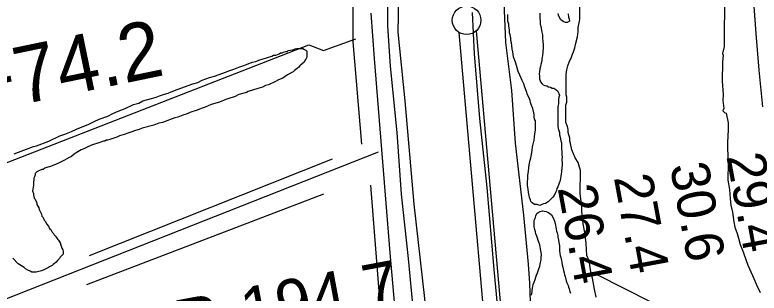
# Model space of a CAD drawing. Extents: x 3324125 to 3362000, y 600753 to 626151.
# Drawn here: x 3331428 to 3332729, y 616457 to 616943 of the extents above; entities that cross this region are included whole.
import ezdxf

# ---------------------------------------------------------------- set-up
doc = ezdxf.new("R2010")
doc.units = 0
for name, color, linetype in [('V-FLOD-BASE', 7, 'Continuous'), ('V-LEVE-TOET', 7, 'Continuous'), ('V-RIVR-RANG', 7, 'Continuous'), ('V-RIVR-RANG-IDEN', 7, 'Continuous'), ('V-ROAD-CNTR', 7, 'Continuous'), ('V-SITE-VEGE', 7, 'Continuous'), ('V-SURV-IDEN', 7, 'Continuous'), ('V-SURV-LINE', 7, 'Continuous'), ('V-TOPO-MAJR', 7, 'Continuous'), ('V-TOPO-SHOR', 7, 'Continuous')]:
    doc.layers.add(name, color=color, linetype=linetype)

msp = doc.modelspace()

# ---------------------------------------------------------------- linework, layer by layer
at = {"layer": 'V-FLOD-BASE'}
msp.add_lwpolyline([(3332227.4, 616947.5), (3332230.4, 616875.1), (3332240.2, 616761.9), (3332252.8, 616641.6), (3332265.3, 616498.5), (3332282.8, 616307), (3332296.8, 616124.8), (3332307.5, 615977.1), (3332326, 615776.8), (3332341.5, 615636.1), (3332349.3, 615584.7), (3332355.5, 615546.7), (3332369.2, 615509.3), (3332410.1, 615416.8), (3332454.9, 615312.6), (3332517, 615173.9)], dxfattribs=at)
at = {"layer": 'V-LEVE-TOET'}
for points in [[(3332098.6, 616972.3), (3332097, 616912.8), (3332109.7, 616793), (3332125.4, 616612.6), (3332143.6, 616447.9), (3332162.1, 616232.5), (3332184.7, 616036.8), (3332201.7, 615777.6), (3332213.1, 615637.5), (3332221.3, 615551.1), (3332240, 615472.2), (3332264.7, 615412.5), (3332328.7, 615293.6), (3332371.9, 615197.6)], [(3332428.3, 615531.7), (3332411.2, 615588.4), (3332406.2, 615631.6), (3332397.3, 615695.8), (3332388.5, 615792.6), (3332387.1, 615828.8), (3332384.4, 615862.8), (3332375.9, 615904.9), (3332364.3, 615994), (3332362, 616032.7), (3332352.6, 616160.4), (3332351.5, 616196.6), (3332346.1, 616277.4), (3332340.9, 616323), (3332330.7, 616391.5), (3332327.8, 616474.5), (3332325.5, 616507.5), (3332317.3, 616593.3), (3332302.9, 616718.9), (3332296.5, 616811.1), (3332286, 616894.6), (3332282.9, 616965.2)]]:
    msp.add_lwpolyline(points, dxfattribs=at)
at = {"layer": 'V-ROAD-CNTR'}
for points in [[(3332050.3, 616945.8), (3332056, 616867), (3332083.1, 616527.3), (3332155.9, 615701.2), (3332162.6, 615620.8), (3332176.4, 615550.1), (3332191.1, 615490.1), (3332204, 615447.5), (3332252.4, 615333.1), (3332828.6, 614063.2)], [(3332062.8, 616703.3), (3331299.1, 616402.5), (3331283.7, 616393.5), (3331269.2, 616382.1), (3331260.5, 616370.6), (3331252.7, 616347.9), (3331246.8, 616320), (3331249.3, 616296.2), (3331258.3, 616256.3), (3331450.3, 615777.5), (3331453.2, 615748.7), (3331451.9, 615720), (3331443.3, 615699.2), (3331428.9, 615681.4), (3331411.3, 615667.7), (3331394.3, 615658.1), (3330239.3, 615193.5), (3328629.8, 614542.4), (3328220.6, 614377)]]:
    msp.add_lwpolyline(points, dxfattribs=at)
at = {"layer": 'V-SITE-VEGE'}
for points in [[(3332427.8, 616523.2), (3332426.6, 616543.8), (3332424, 616563), (3332421.3, 616578.1), (3332418.7, 616600.1), (3332418.8, 616608.3), (3332416.2, 616630.3), (3332416.4, 616671.5), (3332413.8, 616681.1), (3332412.4, 616685.2), (3332407, 616693.5), (3332401.6, 616707.2), (3332398.9, 616718.2), (3332397.6, 616722.3), (3332397.6, 616727.8), (3332394.9, 616737.4), (3332394.9, 616742.9), (3332393.6, 616748.4), (3332390.9, 616755.3), (3332391.1, 616785.5), (3332392.5, 616790.9), (3332392.6, 616799.2), (3332391.2, 616803.3), (3332391.2, 616807.4), (3332391.4, 616823.9), (3332391.4, 616829.4), (3332391.5, 616839), (3332392.9, 616847.2), (3332394.3, 616854), (3332397.1, 616862.2), (3332399.9, 616867.7), (3332402.7, 616874.6), (3332404.1, 616878.7), (3332406.8, 616885.5), (3332408.3, 616893.7), (3332411.1, 616904.7), (3332412.5, 616914.3), (3332412.6, 616921.1), (3332414, 616929.3), (3332415.4, 616934.8), (3332415.6, 616969.1)], [(3332667.9, 616959.3), (3332667.6, 616908.5), (3332667.5, 616887.9), (3332664.7, 616875.6), (3332666, 616872.8), (3332664.6, 616860.5), (3332664.3, 616827.6), (3332665.6, 616804.3), (3332665.5, 616793.3), (3332666.8, 616779.6), (3332665.4, 616775.5), (3332668.1, 616772.7), (3332670.8, 616771.3), (3332674.8, 616754.8), (3332674.8, 616742.5), (3332673.3, 616720.5), (3332673.2, 616709.6), (3332674.4, 616684.9), (3332674.2, 616654.7), (3332676.8, 616638.2), (3332678.1, 616621.8), (3332679.4, 616610.8), (3332682.1, 616598.4), (3332684.7, 616581.9), (3332686, 616572.3), (3332690.1, 616561.3), (3332692.7, 616553.1), (3332695.4, 616542.1), (3332699.5, 616532.5), (3332702.2, 616525.6), (3332708.9, 616506.3), (3332711.6, 616499.5), (3332719.7, 616482.9), (3332723.8, 616471.9), (3332730.5, 616458.2)], [(3331426.5, 616700.5), (3331434.5, 616703.6), (3331448.1, 616708.3), (3331460.8, 616713), (3331465.6, 616714.5), (3331487.2, 616722.4), (3331506.4, 616731.8), (3331515.1, 616734.9), (3331527.1, 616739.6), (3331535.9, 616743.6), (3331557.5, 616752.2), (3331566.3, 616756.9), (3331575.1, 616760.8), (3331590.2, 616766.3), (3331599, 616771), (3331608.6, 616775), (3331620.6, 616779.7), (3331635, 616786.7), (3331644.5, 616789.1), (3331651.7, 616793), (3331666.9, 616796.9), (3331674.9, 616799.2), (3331680.5, 616801.6), (3331689.2, 616804.7), (3331695.6, 616806.3), (3331701.2, 616808.6), (3331711.6, 616812.5), (3331719.6, 616815.7), (3331730.8, 616819.6), (3331738.7, 616822.7), (3331747.5, 616825), (3331755.5, 616829), (3331768.3, 616833.7), (3331777.1, 616836), (3331785, 616839.1), (3331796.2, 616843), (3331803.4, 616846.2), (3331810.6, 616848.5), (3331819.4, 616851.7), (3331826.6, 616854), (3331833, 616856.3), (3331842.5, 616860.3), (3331848.9, 616861.8), (3331854.5, 616864.2), (3331861.7, 616866.5), (3331865.7, 616867.3), (3331869.7, 616868.8), (3331876.9, 616871.2), (3331880.1, 616872.8), (3331884, 616872.7), (3331889.6, 616875.1), (3331892, 616876.7), (3331895.2, 616876.7), (3331897.6, 616878.2), (3331901.6, 616879), (3331904, 616879), (3331905.6, 616880.6), (3331913.6, 616882.1), (3331917.6, 616883.7), (3331920.8, 616884.5), (3331931.1, 616884.4), (3331934.3, 616882.8), (3331936.7, 616881.2), (3331938.2, 616879.6)], [(3331938.2, 616879.6), (3331938.2, 616869.2), (3331936.6, 616866), (3331935, 616863.6), (3331933.3, 616860.5), (3331930.1, 616857.3), (3331926.1, 616854.1), (3331924.5, 616851.8), (3331921.3, 616849.4), (3331916.5, 616846.2), (3331914.1, 616843.9), (3331904.5, 616838.4), (3331900.5, 616835.2), (3331896.5, 616832.8), (3331888.5, 616829.7), (3331883.7, 616826.5), (3331871, 616821), (3331866.2, 616819.5), (3331860.6, 616817.1), (3331852.6, 616814.8), (3331835.8, 616809.3), (3331832.6, 616807.8), (3331819.1, 616803.9), (3331811.9, 616799.9), (3331805.5, 616798.4), (3331796.7, 616795.2), (3331785.5, 616790.5), (3331771.2, 616786.6), (3331760.8, 616781.9), (3331753.6, 616779.6), (3331746.4, 616776.5), (3331735.2, 616773.3), (3331728.8, 616770.2), (3331721.7, 616767.8), (3331712.9, 616764.7), (3331707.3, 616763.2), (3331685.7, 616755.3), (3331679.4, 616753.8), (3331670.6, 616750.7), (3331650.6, 616745.2), (3331645, 616742.9), (3331638.7, 616741.3), (3331630.7, 616738.2), (3331625.1, 616736.6), (3331618.7, 616734.3), (3331610.7, 616731.9), (3331605.9, 616729.6), (3331593.9, 616725.7), (3331590, 616724.1), (3331587.6, 616724.1), (3331585.2, 616722.5), (3331582.8, 616722.5), (3331576.4, 616720.2), (3331562, 616715.5), (3331553.2, 616711.6), (3331548.4, 616709.2), (3331543.6, 616707.7), (3331538, 616703.7), (3331534.9, 616702.1), (3331531.6, 616699.8), (3331526.8, 616695.8), (3331522.9, 616694.3), (3331514.9, 616689.5), (3331502.1, 616683.2), (3331488.5, 616677.8), (3331485.3, 616677), (3331480.5, 616675.4), (3331477.3, 616673), (3331474.9, 616673.1), (3331470.9, 616671.5), (3331468.5, 616669.9), (3331466.1, 616669.1), (3331463.7, 616666), (3331463.7, 616663.6), (3331462.1, 616660.4), (3331461.3, 616658), (3331461.3, 616655.6), (3331460.4, 616650.1), (3331460.4, 616645.3), (3331458.8, 616635.7), (3331460.3, 616630.9), (3331460.3, 616628.6), (3331461.9, 616623), (3331463.4, 616621.4), (3331465, 616617.4), (3331466.6, 616614.2), (3331466.6, 616611.8), (3331469.7, 616606.2), (3331470.5, 616603), (3331474.4, 616595), (3331475.2, 616591.8), (3331477.6, 616589.4), (3331479.1, 616584.6), (3331481.5, 616582.2)], [(3331481.5, 616582.2), (3331483.1, 616578.2), (3331487, 616574.2), (3331488.6, 616570.2), (3331491, 616568.6), (3331493.3, 616563.8), (3331495.7, 616561.4), (3331496.5, 616559), (3331498.9, 616556.6), (3331501.2, 616553.4), (3331502.8, 616551), (3331504.4, 616549.4), (3331506, 616547), (3331507.5, 616543.8), (3331507.5, 616541.4), (3331509.1, 616539.8), (3331509.9, 616535.8), (3331511.5, 616532.6), (3331512.2, 616529.4), (3331512.2, 616525.5), (3331509, 616521.5), (3331507.4, 616519.9), (3331505.8, 616517.5), (3331502.6, 616514.4), (3331500.2, 616511.2), (3331497, 616508.8), (3331494.6, 616507.3), (3331493, 616505.7), (3331488.2, 616503.3), (3331486.6, 616501.7), (3331478.6, 616497.8), (3331474.6, 616496.2), (3331465, 616493.9), (3331457.8, 616494), (3331454.7, 616495.6), (3331450.7, 616497.2), (3331446.7, 616499.6), (3331444.3, 616502), (3331434, 616508.4), (3331424.5, 616518.1)], [(3332443.8, 616450.4), (3332441.2, 616464.2), (3332437.2, 616483.4), (3332434.5, 616494.4), (3332431.9, 616513.6), (3332427.8, 616523.2)]]:
    msp.add_lwpolyline(points, dxfattribs=at)
at = {"layer": 'V-SURV-LINE'}
for points in [[(3332271.7, 616150.7), (3332204.2, 616912.5)], [(3332234.1, 616915.1), (3332301.6, 616153.4)]]:
    msp.add_lwpolyline(points, dxfattribs=at)
msp.add_circle((3332217.4, 616933.7), 25, dxfattribs=at)
at = {"layer": 'V-TOPO-MAJR'}
for points in [[(3332718.4, 616974.5), (3332723, 616910.5), (3332728.3, 616846.5), (3332734.3, 616782.6)], [(3332738, 616055.9), (3332708.7, 616129.9), (3332676.5, 616202.7), (3332642.1, 616274.7), (3332576.3, 616405.6), (3332573.1, 616411.2), (3332569.5, 616416.6), (3332565.5, 616421.6), (3332561, 616426.3), (3332556.2, 616430.6), (3332551.1, 616434.6), (3332545.7, 616438.2), (3332540, 616441.4), (3332445.4, 616489.4), (3332444.4, 616489.8), (3332442.3, 616490.2), (3332438.9, 616489.9)]]:
    msp.add_lwpolyline(points, dxfattribs=at)
at = {"layer": 'V-TOPO-SHOR'}
for p, q in [((3332018.6, 616896.1), (3332033.9, 616717.1)), ((3331558.4, 616522.8), (3331982.8, 616691.5)), ((3331967.5, 616630.2), (3331553.3, 616471.7))]:
    msp.add_line(p, q, dxfattribs=at)
for points in [[(3332315.2, 618946.6), (3332274.3, 618588.6), (3332269.2, 618394.3), (3332264.1, 618179.6), (3332284.5, 617975), (3332294.7, 617842.1), (3332294.7, 617790.9), (3332269.2, 617693.8), (3332197.6, 617525), (3332059.5, 617197.8), (3332028.8, 617080.2), (3332018.6, 616977.9), (3332018.6, 616896.1)], [(3332079.8, 617015.2), (3332079.2, 616924), (3332083.6, 616853.8), (3332095.6, 616737.5), (3332102.8, 616629.9), (3332115.3, 616517.9), (3332127.6, 616387.6), (3332144.3, 616212.6), (3332159.4, 616070), (3332174.3, 615861.2), (3332184.7, 615740.4), (3332198.2, 615602.9), (3332211.5, 615516.4), (3332226.3, 615457), (3332245.5, 615405.9), (3332276.9, 615338.4), (3332310.8, 615281.2), (3332354.3, 615179.4)], [(3332292.7, 616912), (3332292.7, 616916.7), (3332291.2, 616923.1), (3332291.2, 616927.1), (3332289.6, 616931.9), (3332289.7, 616938.3), (3332289.7, 616943.8)], [(3332345.5, 616945.9), (3332345.4, 616937.1), (3332346.2, 616932.3), (3332346.1, 616927.5), (3332347.7, 616919.6), (3332348.5, 616915.6), (3332350, 616907.6), (3332350, 616902), (3332350.7, 616897.2), (3332351.5, 616890.9), (3332351.5, 616885.3), (3332350.6, 616878.9), (3332349.8, 616871.8), (3332348.9, 616867), (3332348.9, 616863), (3332347.3, 616856.6), (3332346.5, 616852.7), (3332345.6, 616848.7), (3332344.8, 616843.9), (3332344, 616839.9), (3332344.8, 616836), (3332344.7, 616831.2), (3332346.3, 616826.4), (3332348.7, 616823.2), (3332351, 616820.8), (3332354.2, 616820), (3332357.4, 616819.1), (3332360.6, 616817.5), (3332363.8, 616816.7), (3332366.9, 616815.1), (3332370.1, 616815.1), (3332373.3, 616812.7), (3332376.5, 616810.3), (3332378.8, 616805.5), (3332379.6, 616802.3), (3332378.8, 616799.1)], [(3332394.8, 616944.8), (3332395.6, 616939.2), (3332396.4, 616936), (3332397.2, 616932), (3332393.2, 616929.6), (3332390, 616929.7), (3332386, 616931.3), (3332382, 616934.5), (3332379.7, 616938.5), (3332378.1, 616942.5), (3332377.3, 616945.7)], [(3332378.8, 616799.1), (3332378, 616795.1), (3332377.9, 616787.9), (3332377.1, 616783.2), (3332377, 616777.6), (3332377, 616770.4), (3332377, 616765.7), (3332376.9, 616760.1), (3332376.9, 616753.7), (3332376.9, 616748.9), (3332377.6, 616744.9), (3332380, 616737.8), (3332379.9, 616733.8), (3332380.7, 616729.8), (3332382.3, 616723.4), (3332383, 616719.4), (3332383, 616711.4), (3332383, 616708.3), (3332383.7, 616704.3), (3332383.7, 616698.7), (3332384.5, 616694.7), (3332383.7, 616690.7), (3332384.4, 616684.4), (3332384.4, 616680.4), (3332383.6, 616676.4), (3332383.5, 616669.2), (3332382.7, 616665.3), (3332381.9, 616661.3), (3332381.8, 616658.1), (3332381, 616654.1), (3332379.4, 616649.3), (3332377, 616643), (3332375.4, 616639.8), (3332374.5, 616636.6), (3332372.9, 616632.7), (3332370.5, 616627.9), (3332368.1, 616624.7), (3332365.7, 616622.3), (3332363.3, 616620), (3332360.1, 616616.8), (3332355.3, 616613.7), (3332352.1, 616612.9), (3332348.9, 616612.1), (3332345.7, 616610.5), (3332340.1, 616612.2), (3332336.1, 616612.2), (3332332.2, 616614.6), (3332329.8, 616617), (3332329, 616620.2), (3332327.5, 616624.2), (3332326.7, 616627.4), (3332325.9, 616633), (3332325.2, 616638.5), (3332323.6, 616644.9), (3332323.7, 616652.1), (3332324.5, 616656.9), (3332324.5, 616662.4), (3332325.4, 616670.4), (3332326.2, 616676), (3332327, 616681.5), (3332328.7, 616689.5), (3332329.5, 616693.5), (3332331.1, 616699), (3332332, 616707), (3332332.8, 616712.6), (3332333.6, 616717.3), (3332335.3, 616724.5), (3332336.1, 616730.1), (3332336.9, 616735.6), (3332337.8, 616742), (3332337.8, 616746.8), (3332337.8, 616751.6), (3332337.9, 616757.9), (3332336.3, 616761.1), (3332335.5, 616765.1), (3332335.6, 616769.1), (3332334.8, 616772.3), (3332333.2, 616779.5), (3332330.1, 616786.7), (3332329.3, 616789.9), (3332328.6, 616793.8), (3332326.2, 616799.4), (3332323.8, 616803.4), (3332322.3, 616809), (3332319.1, 616817), (3332317.6, 616822.6), (3332314.4, 616828.2), (3332310.5, 616837.8), (3332307.4, 616844.2), (3332305.8, 616850.5), (3332303.5, 616858.5), (3332301.1, 616864.9), (3332299.6, 616869.7), (3332298, 616878.5), (3332297.3, 616883.3), (3332296.5, 616889.6), (3332295.8, 616894.4), (3332295, 616898.4), (3332295, 616902.4), (3332293.5, 616908), (3332292.7, 616912)], [(3329983.4, 616216), (3330295.4, 616343.8), (3330356.7, 616262), (3331088, 616558.6), (3331941.9, 616891), (3331967.5, 616880.7), (3332023.7, 616901.2)], [(3332049.3, 616645.5), (3332100.4, 616001.2), (3332105.5, 615873.4), (3332126, 615694.4), (3332136.2, 615576.8), (3332182.2, 615454.1), (3332264.1, 615239.3), (3332483.9, 614768.9), (3332673.1, 614344.5), (3332708.9, 614267.7)], [(3332338.4, 616560.9), (3332337.6, 616564.1), (3332336.5, 616568.5), (3332335.3, 616572.9), (3332335.3, 616576.9), (3332335.3, 616580.8), (3332335.8, 616584), (3332337, 616587.6), (3332338.2, 616592.4), (3332340.2, 616596), (3332342.6, 616597.9), (3332346.2, 616599.5), (3332349.8, 616600.7), (3332353, 616600.2), (3332356.6, 616599.8), (3332359.4, 616598.6), (3332362.1, 616597), (3332365.7, 616594.2), (3332368.1, 616589.8), (3332369.6, 616585.8), (3332370.8, 616583), (3332372, 616579), (3332372.7, 616575.8), (3332373.1, 616572.2), (3332373.9, 616569.1), (3332374.7, 616565.5), (3332375.8, 616562.3), (3332376.6, 616557.9), (3332377, 616554.7), (3332377.8, 616549.9), (3332378.5, 616545.5), (3332379.7, 616539.5), (3332379.6, 616534.4), (3332380, 616531.2), (3332380.4, 616526.4), (3332381.2, 616522.8), (3332381.9, 616519.2), (3332383.1, 616514), (3332383.9, 616510.4), (3332384.6, 616506.5), (3332385.8, 616502.5), (3332387, 616496.9), (3332387.7, 616492.5), (3332388.5, 616489.3), (3332389.7, 616486.5), (3332390.9, 616481.7), (3332391.6, 616478.5), (3332392.8, 616475.3), (3332394.8, 616470.5), (3332395.5, 616467.4), (3332396.7, 616464.6), (3332397.9, 616460.2), (3332399.1, 616457)], [(3332330.9, 616453.4), (3332331.8, 616459.4), (3332332.2, 616462.6), (3332333, 616469), (3332333.8, 616472.1), (3332335.5, 616476.1), (3332337.1, 616480.9), (3332338.7, 616485.2), (3332339.5, 616488.4), (3332341.5, 616492.4), (3332343.2, 616498), (3332345.2, 616504.3), (3332346, 616507.5), (3332346.4, 616510.7), (3332347.7, 616515.5), (3332347.7, 616518.6), (3332348.1, 616525.4), (3332347.4, 616531), (3332346.6, 616534.6), (3332345.4, 616541.4), (3332343.9, 616546.1), (3332342.7, 616548.9), (3332341.1, 616553.3), (3332340, 616556.5), (3332338.4, 616560.9)]]:
    msp.add_lwpolyline(points, dxfattribs=at)

# ---------------------------------------------------------------- texts
at = {"layer": 'V-RIVR-RANG'}
for s, p in [('29.4', (3332671.2, 616696.3)), ('30.6', (3332572.6, 616679.7)), ('27.4', (3332474.6, 616659.4)), ('26.4', (3332376.4, 616641))]:
    msp.add_text(s, height=67, rotation=280.4683, dxfattribs=at).set_placement(p)
at = {"layer": 'V-RIVR-RANG-IDEN'}
msp.add_text('R-194.7', height=83, rotation=10.6106, dxfattribs=at).set_placement((3331716.5, 616361.3))
at = {"layer": 'V-SURV-IDEN'}
msp.add_text('5200+74.2', height=100, rotation=11.6907, dxfattribs=at).set_placement((3331069.8, 616709.7))

doc.saveas('drawing.dxf')
